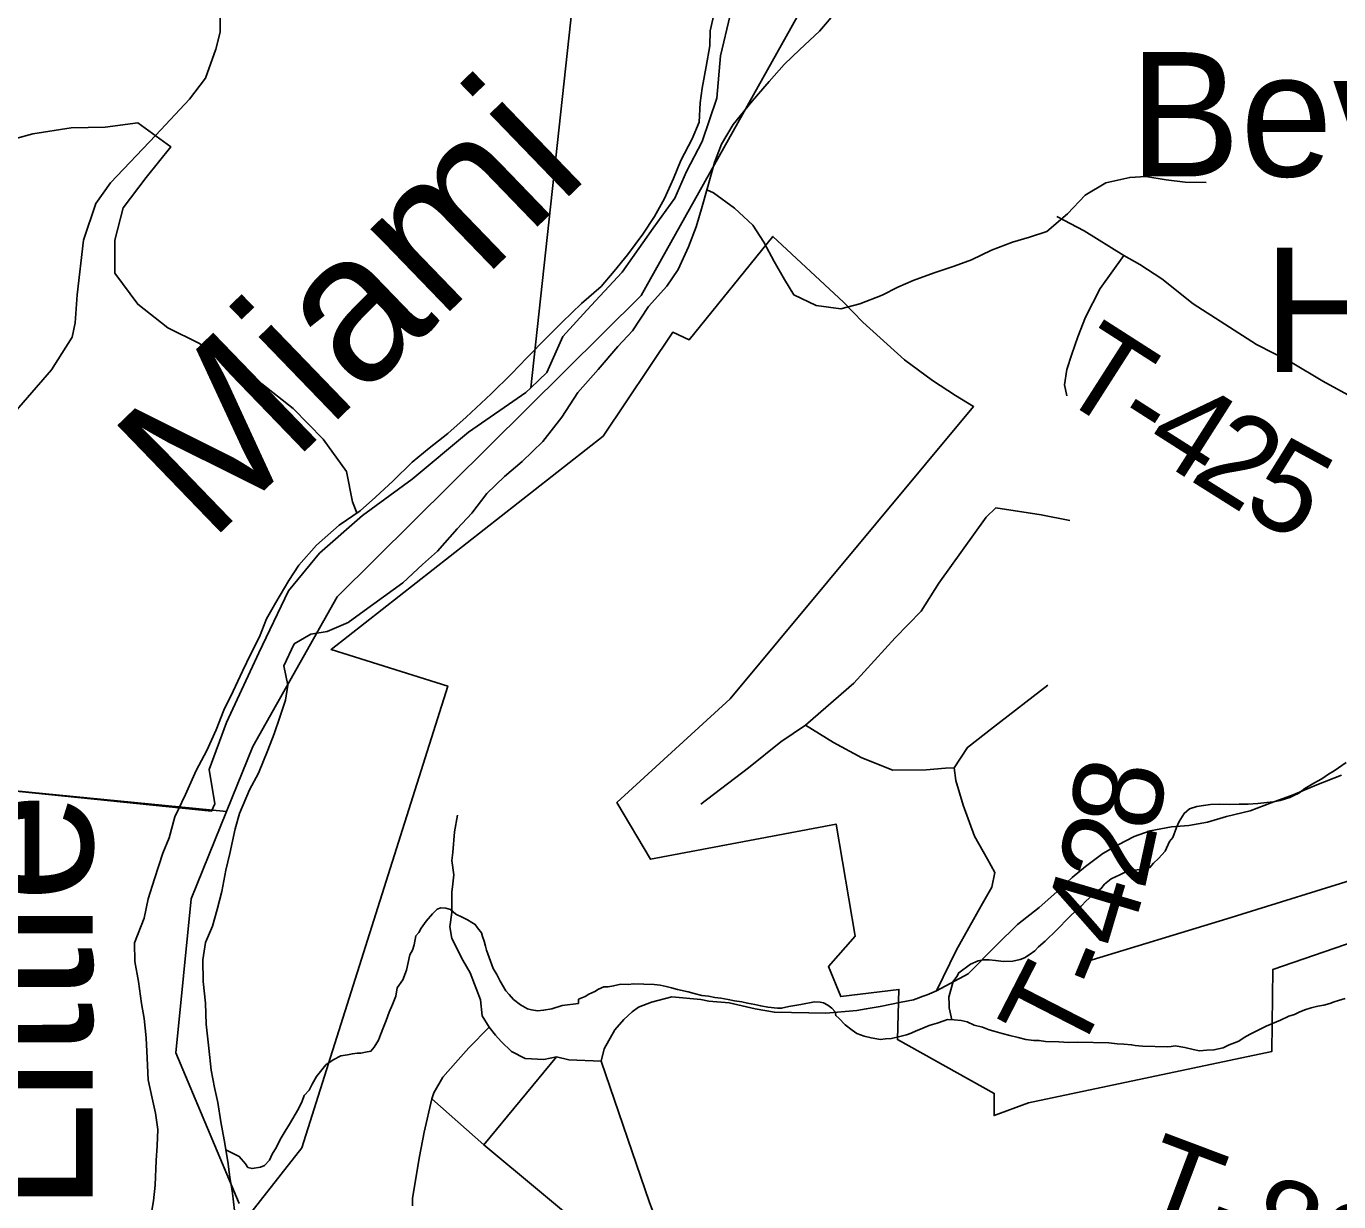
# Model space of a CAD drawing. Extents: x 0 to 34, y 0 to 22.
# Drawn here: x 6.3755 to 6.7924, y 19.556 to 19.9293 of the extents above; entities that cross this region are included whole.
import ezdxf

# ---------------------------------------------------------------- set-up
doc = ezdxf.new("R2010")
doc.units = 0
for name, color, linetype in [('GM_X_City_Street', 7, 'Continuous'), ('GM_X_Corporation', 7, 'Continuous'), ('GM_X_County_Road', 7, 'Continuous'), ('GM_X_Major_River', 7, 'Continuous'), ('GM_X_Major_River_Text', 7, 'Continuous'), ('GM_X_Minor_River', 7, 'Continuous'), ('GM_X_Section', 7, 'Continuous'), ('GM_X_State_Route', 7, 'Continuous'), ('GM_X_Township_Road', 7, 'Continuous'), ('GM_X_Township_Road_Text', 7, 'Continuous'), ('GM_X_Unincorporated_Text', 7, 'Continuous'), ('SH_Cut_Line', 7, 'Continuous')]:
    doc.layers.add(name, color=color, linetype=linetype)

msp = doc.modelspace()

# ---------------------------------------------------------------- linework, layer by layer
at = {"layer": 'GM_X_City_Street'}
msp.add_line((6.52085, 19.57407), (6.54387, 19.60201), dxfattribs=at)
for points in [[(6.55805, 19.60066), (6.54776, 19.6011), (6.54387, 19.60201), (6.53985, 19.60113), (6.53389, 19.60145), (6.52962, 19.60374), (6.52633, 19.60689), (6.52447, 19.60887), (6.5225, 19.61144), (6.5203, 19.61501), (6.51977, 19.62012), (6.51836, 19.62372), (6.51647, 19.62874), (6.51412, 19.63267), (6.51067, 19.63957), (6.51004, 19.64333), (6.51067, 19.64788), (6.51067, 19.65432), (6.51098, 19.65698), (6.5113, 19.65981), (6.51067, 19.66436), (6.51098, 19.66687), (6.51145, 19.67346), (6.51239, 19.67879)], [(6.49811, 19.55474), (6.49811, 19.55603), (6.49813, 19.55709), (6.50035, 19.57038), (6.50182, 19.57804), (6.50425, 19.5887), (6.50497, 19.59062), (6.50781, 19.59555), (6.51176, 19.6001), (6.51603, 19.60492), (6.5225, 19.61144)], [(6.58393, 19.52802), (6.57342, 19.55579), (6.55805, 19.60066)], [(6.5555, 19.54512), (6.52085, 19.57407), (6.50425, 19.5887)]]:
    msp.add_lwpolyline(points, dxfattribs=at)
at = {"layer": 'GM_X_Corporation'}
for points in [[(5.43226, 19.77875), (6.32743, 19.69086), (6.43909, 19.6799), (6.44745, 19.70059), (6.47425, 19.74809), (6.57081, 19.84384), (6.62479, 19.94035), (6.6725, 19.98366), (6.72231, 20.02185), (6.73923, 20.06935), (6.75063, 20.11704), (6.77249, 20.16568), (6.77819, 20.26107)], [(6.77819, 20.26107), (6.77249, 20.16568), (6.75063, 20.11704), (6.73923, 20.06935), (6.72231, 20.02185), (6.6725, 19.98366), (6.62479, 19.94035), (6.57081, 19.84384), (6.47425, 19.74809), (6.44745, 19.70059), (6.43909, 19.6799), (6.42788, 19.65215), (6.42294, 19.60331), (6.4431, 19.55544)], [(6.42905, 19.52976), (6.46297, 19.57308), (6.50933, 19.71976), (6.47227, 19.73135), (6.55869, 19.7991), (6.58087, 19.83221), (6.586, 19.82974), (6.61262, 19.86261), (6.63506, 19.84168), (6.64121, 19.83532), (6.65444, 19.82341), (6.66327, 19.81688), (6.67062, 19.81202), (6.67638, 19.80856), (6.59901, 19.7157), (6.56309, 19.68276), (6.57372, 19.66477), (6.63267, 19.67592), (6.63877, 19.64038), (6.63032, 19.63075), (6.63419, 19.62114), (6.65266, 19.62343), (6.65217, 19.60748), (6.68293, 19.5904), (6.6829, 19.58337), (6.69384, 19.58741), (6.77115, 19.60371), (6.77138, 19.62974), (6.80742, 19.64214)], [(6.4431, 19.55544), (6.42294, 19.60331), (6.42788, 19.65215), (6.43909, 19.6799), (6.32743, 19.69086), (5.43226, 19.77875)]]:
    msp.add_lwpolyline(points, dxfattribs=at)
at = {"layer": 'GM_X_County_Road'}
for points in [[(6.66032, 19.62128), (6.66162, 19.62176), (6.66458, 19.62303), (6.67461, 19.62843), (6.68371, 19.63757), (6.69029, 19.64408), (6.6972, 19.64945), (6.70285, 19.65447), (6.70772, 19.65902), (6.71195, 19.66247), (6.71744, 19.66655), (6.72231, 19.66938), (6.72733, 19.67204), (6.7325, 19.67377), (6.73925, 19.67502), (6.74474, 19.6755), (6.7507, 19.67659), (6.75666, 19.67832), (6.76419, 19.6802), (6.77094, 19.68271), (6.77784, 19.68522), (6.78537, 19.68836), (6.79322, 19.6915)], [(6.55805, 19.60066), (6.55899, 19.60458), (6.56244, 19.61055), (6.56526, 19.61384), (6.56793, 19.61635), (6.56997, 19.61776), (6.57405, 19.61933), (6.58048, 19.62106), (6.58976, 19.62021), (6.59222, 19.61973), (6.59868, 19.61917), (6.607, 19.61729), (6.61311, 19.61619), (6.6294, 19.6159), (6.63924, 19.61676), (6.64225, 19.61725), (6.64668, 19.61803), (6.65334, 19.61934), (6.6573, 19.62015), (6.66032, 19.62128)]]:
    msp.add_lwpolyline(points, dxfattribs=at)
at = {"layer": 'GM_X_Major_River'}
for points in [[(6.59412, 19.93396), (6.59266, 19.92791), (6.59256, 19.92316), (6.59147, 19.91653), (6.59018, 19.90971), (6.58951, 19.90498), (6.58919, 19.8989), (6.58698, 19.89362), (6.58342, 19.88666), (6.58102, 19.88101), (6.57822, 19.87461), (6.57506, 19.86897), (6.57133, 19.86334), (6.56645, 19.85679), (6.56216, 19.85156), (6.55806, 19.8467), (6.55187, 19.84131), (6.54567, 19.83536), (6.54082, 19.83052), (6.53441, 19.824), (6.52956, 19.81896), (6.52316, 19.81263), (6.51522, 19.80519), (6.50941, 19.79999), (6.50342, 19.79536), (6.49801, 19.79091), (6.492, 19.78495), (6.48638, 19.77974), (6.48154, 19.77547), (6.4748, 19.77086), (6.46764, 19.76454), (6.462, 19.7582), (6.45886, 19.75332), (6.45472, 19.74637), (6.45176, 19.74111), (6.44955, 19.73545), (6.44677, 19.73), (6.44419, 19.72454), (6.4412, 19.71814), (6.43822, 19.71212), (6.43581, 19.70589), (6.43282, 19.6993), (6.42945, 19.69291), (6.42606, 19.68538), (6.42268, 19.67822), (6.42083, 19.67161), (6.41882, 19.66671), (6.41618, 19.65859), (6.41414, 19.65216), (6.41287, 19.64611), (6.40985, 19.63819), (6.40992, 19.63229), (6.41111, 19.62599), (6.41209, 19.61894), (6.41294, 19.61417), (6.41357, 19.60808), (6.41381, 19.60161), (6.41423, 19.59476), (6.41543, 19.58884), (6.41646, 19.58407), (6.4173, 19.57891), (6.417, 19.57379), (6.4167, 19.56904), (6.41635, 19.56126), (6.41586, 19.55632), (6.41477, 19.55007)], [(6.44193, 19.55047), (6.44096, 19.55866), (6.44013, 19.56381), (6.43947, 19.56877), (6.4383, 19.57563), (6.43728, 19.58136), (6.43628, 19.58746), (6.43524, 19.59223), (6.43422, 19.59777), (6.43343, 19.60482), (6.43264, 19.61244), (6.43241, 19.61909), (6.43161, 19.62595), (6.43157, 19.6328), (6.43244, 19.63829), (6.43465, 19.64357), (6.43609, 19.64886), (6.43754, 19.65453), (6.43883, 19.66135), (6.44008, 19.66665), (6.44177, 19.67441), (6.4432, 19.67932), (6.44641, 19.68686), (6.44918, 19.69212), (6.45218, 19.69947), (6.45419, 19.70456), (6.45602, 19.70985), (6.45784, 19.71532), (6.45851, 19.72006), (6.45732, 19.72617), (6.46051, 19.73314), (6.46589, 19.73626), (6.47103, 19.7371), (6.47774, 19.74001), (6.48275, 19.7437), (6.49509, 19.75257), (6.50129, 19.75834), (6.50613, 19.76261), (6.51236, 19.76971), (6.51702, 19.77474), (6.52171, 19.78092), (6.52733, 19.78631), (6.53294, 19.79114), (6.53953, 19.79747), (6.54558, 19.80514), (6.55069, 19.81302), (6.55711, 19.8203), (6.56334, 19.82758), (6.56801, 19.83262), (6.57311, 19.8403), (6.57895, 19.84684), (6.58248, 19.85209), (6.58586, 19.85924), (6.58828, 19.86565), (6.58992, 19.87132), (6.59197, 19.8785), (6.59403, 19.88606), (6.59625, 19.89191), (6.59999, 19.89811), (6.60604, 19.90559), (6.61148, 19.91175), (6.61616, 19.91716), (6.6212, 19.922), (6.6274, 19.92777), (6.63304, 19.9343)]]:
    msp.add_lwpolyline(points, dxfattribs=at)
at = {"layer": 'GM_X_Minor_River'}
for points in [[(6.4805, 19.77476), (6.47909, 19.77826), (6.47718, 19.78796), (6.46975, 19.79823), (6.46022, 19.80793), (6.45031, 19.81573), (6.44059, 19.82201), (6.4303, 19.82866), (6.42039, 19.83361), (6.41086, 19.84103), (6.40362, 19.85092), (6.40362, 19.86138), (6.40628, 19.87165), (6.41352, 19.88135), (6.42133, 19.89105), (6.41085, 19.89865), (6.40056, 19.89732), (6.3897, 19.89713), (6.3775, 19.89523), (6.36664, 19.89219)], [(6.59165, 19.87737), (6.59371, 19.87649), (6.60045, 19.8716), (6.60623, 19.86617), (6.60972, 19.86078), (6.61302, 19.85463), (6.61632, 19.84887), (6.61926, 19.84406), (6.62641, 19.84069), (6.63417, 19.83959), (6.64028, 19.84118), (6.64736, 19.84389), (6.65235, 19.84646), (6.65714, 19.84864), (6.66384, 19.85098), (6.67015, 19.85314), (6.6757, 19.85512), (6.68203, 19.85823), (6.68873, 19.86076), (6.69408, 19.86237), (6.69962, 19.86416), (6.70619, 19.86973), (6.71182, 19.8757), (6.71836, 19.87957), (6.72599, 19.88132), (6.73113, 19.8816), (6.73756, 19.88052), (6.74362, 19.87983), (6.75027, 19.8797)], [(6.66947, 19.61378), (6.66856, 19.61759), (6.66859, 19.61873), (6.66846, 19.62101), (6.66909, 19.62327), (6.66991, 19.6259), (6.67109, 19.62758), (6.67169, 19.6287), (6.67537, 19.63145), (6.67786, 19.63252), (6.67939, 19.63286), (6.68129, 19.63281), (6.68337, 19.63257), (6.68584, 19.63231), (6.68888, 19.63242), (6.69117, 19.63293), (6.69251, 19.63346), (6.69405, 19.63437), (6.69579, 19.63565), (6.69697, 19.63695), (6.6991, 19.63879), (6.7028, 19.6423), (6.7067, 19.64637), (6.70903, 19.64858), (6.71059, 19.64987), (6.71215, 19.65153), (6.7139, 19.65319), (6.71564, 19.65466), (6.7168, 19.65539), (6.71798, 19.65688), (6.72011, 19.65853), (6.7228, 19.65979), (6.72453, 19.66069), (6.72682, 19.6612), (6.72911, 19.66152), (6.73121, 19.66184), (6.73236, 19.66219), (6.73353, 19.66349), (6.73509, 19.66496), (6.73723, 19.66737), (6.73864, 19.67037), (6.73962, 19.67167), (6.74084, 19.67486), (6.74165, 19.67674), (6.74323, 19.67935), (6.74498, 19.68082), (6.74728, 19.68152), (6.74937, 19.68184), (6.75166, 19.68216), (6.75451, 19.68228), (6.75774, 19.68219), (6.76078, 19.6823), (6.76363, 19.68223), (6.76667, 19.68253), (6.76953, 19.68283), (6.77162, 19.68297), (6.77372, 19.68348), (6.77545, 19.684), (6.77678, 19.68435), (6.77813, 19.68507), (6.77967, 19.68579), (6.78161, 19.68726), (6.78449, 19.68889), (6.787, 19.69034), (6.78913, 19.6918), (6.79086, 19.69289), (6.79473, 19.69545)], [(6.43884, 19.57246), (6.44309, 19.5704), (6.44512, 19.56807), (6.44585, 19.56691), (6.44717, 19.5665), (6.44984, 19.567), (6.45118, 19.56753), (6.45274, 19.5692), (6.45355, 19.57107), (6.45493, 19.57331), (6.45614, 19.57575), (6.45772, 19.57836), (6.45911, 19.5806), (6.46189, 19.58546), (6.46309, 19.58789), (6.46371, 19.58977), (6.46527, 19.59143), (6.46626, 19.5933), (6.46765, 19.59573), (6.4706, 19.59945), (6.47292, 19.60109), (6.47542, 19.60236), (6.47752, 19.60268), (6.47904, 19.60302), (6.48057, 19.60317), (6.48171, 19.60314), (6.48323, 19.60348), (6.48495, 19.60381), (6.48593, 19.60512), (6.48732, 19.60735), (6.48793, 19.60905), (6.48894, 19.61148), (6.48975, 19.61355), (6.49077, 19.61618), (6.49178, 19.61862), (6.4928, 19.62124), (6.49324, 19.62389), (6.49502, 19.62649), (6.49623, 19.6295), (6.49731, 19.6344), (6.4981, 19.63589), (6.49872, 19.63758), (6.49917, 19.64042), (6.50014, 19.64153), (6.50094, 19.64284), (6.50251, 19.64507), (6.50447, 19.64748), (6.50603, 19.64896), (6.50718, 19.64931), (6.5087, 19.64927), (6.51021, 19.64885), (6.51188, 19.64729), (6.51413, 19.64628), (6.51563, 19.64549), (6.51694, 19.64469), (6.51806, 19.64409), (6.51879, 19.64294), (6.52008, 19.64139), (6.52043, 19.64024), (6.52096, 19.63871), (6.52131, 19.63718), (6.52165, 19.63585), (6.52379, 19.6301), (6.52488, 19.62818), (6.52596, 19.62606), (6.52778, 19.62298), (6.52889, 19.62182), (6.53018, 19.62027), (6.53242, 19.6185), (6.53467, 19.6173), (6.53599, 19.61689), (6.53788, 19.61665), (6.53978, 19.61679), (6.54245, 19.61729), (6.54571, 19.61834), (6.55085, 19.61897), (6.55089, 19.62029), (6.553, 19.62119), (6.55416, 19.62191), (6.55608, 19.62281), (6.55723, 19.62354), (6.55896, 19.62425), (6.56029, 19.62422), (6.56201, 19.62455), (6.5643, 19.62506), (6.56677, 19.625), (6.56829, 19.62515), (6.57493, 19.62497), (6.57683, 19.62473), (6.57871, 19.62431), (6.58041, 19.62388), (6.5823, 19.62345), (6.5857, 19.62261), (6.58759, 19.62218), (6.59004, 19.62154), (6.59212, 19.6213), (6.5942, 19.62087), (6.59609, 19.62063), (6.59836, 19.62019), (6.60044, 19.61976), (6.60271, 19.61951)], [(6.60271, 19.61951), (6.6046, 19.61908), (6.60687, 19.61864), (6.60875, 19.61821), (6.61102, 19.61777), (6.61406, 19.6175), (6.61538, 19.61747), (6.61768, 19.61798), (6.62149, 19.61864), (6.62588, 19.61947), (6.62759, 19.61943), (6.62872, 19.61921), (6.63003, 19.61841), (6.63134, 19.61743), (6.63245, 19.61626), (6.63261, 19.61512), (6.63372, 19.61415), (6.63557, 19.6122), (6.63781, 19.61044), (6.6393, 19.60945), (6.64156, 19.60863), (6.64382, 19.608), (6.64685, 19.60755), (6.64837, 19.6077), (6.65027, 19.60784), (6.65295, 19.60852), (6.65505, 19.60904), (6.65658, 19.60957), (6.65812, 19.61028), (6.66004, 19.61099), (6.66119, 19.61153), (6.66254, 19.61206), (6.66483, 19.61276), (6.66694, 19.61347), (6.66809, 19.61382), (6.67017, 19.61376), (6.67245, 19.61351), (6.67434, 19.61308), (6.67659, 19.61208), (6.67923, 19.61144), (6.6813, 19.61063), (6.68318, 19.61001), (6.68545, 19.60938), (6.6879, 19.60875), (6.69054, 19.60811), (6.69299, 19.60748), (6.69546, 19.60722), (6.69717, 19.60718), (6.69925, 19.60693), (6.70342, 19.60682), (6.70664, 19.60655), (6.7095, 19.60667), (6.71937, 19.60641), (6.72202, 19.60615), (6.72411, 19.60609), (6.72657, 19.60584), (6.7277, 19.60562), (6.72997, 19.60537), (6.73795, 19.60516), (6.73909, 19.60532), (6.74042, 19.60548), (6.74345, 19.60502), (6.74609, 19.60438), (6.74817, 19.60395), (6.75045, 19.60408), (6.75273, 19.60421), (6.7556, 19.60489), (6.75752, 19.60579), (6.75925, 19.6065), (6.76059, 19.60704), (6.76233, 19.60813), (6.76426, 19.60922), (6.76926, 19.61174), (6.77386, 19.6137), (6.77655, 19.61496), (6.77828, 19.61549), (6.77981, 19.6162), (6.78154, 19.61692), (6.78365, 19.61762), (6.78575, 19.61813), (6.78766, 19.61846), (6.78957, 19.61898), (6.79091, 19.61951), (6.79225, 19.61986), (6.79436, 19.62056)]]:
    msp.add_lwpolyline(points, dxfattribs=at)
at = {"layer": 'GM_X_Section'}
msp.add_lwpolyline([(5.98888, 20.23965), (6.57479, 20.17408), (6.53576, 19.81452), (6.53419, 19.81301), (6.51594, 19.8004), (6.49801, 19.78545), (6.48222, 19.77393), (6.46855, 19.76197), (6.45874, 19.75002), (6.44934, 19.73038), (6.4391, 19.70818), (6.43355, 19.69324), (6.43532, 19.6824), (6.43432, 19.68006), (5.94132, 19.73044)], close=True, dxfattribs=at)
msp.add_lwpolyline([(6.5991, 19.93291), (6.596, 19.9199), (6.59478, 19.90648), (6.59015, 19.89275), (6.58522, 19.88319), (6.58146, 19.87475), (6.57464, 19.86523), (6.5647, 19.85122), (6.55347, 19.83914), (6.54592, 19.83077), (6.54085, 19.81941), (6.53576, 19.81452), (6.57479, 20.17408)], dxfattribs=at)
at = {"layer": 'GM_X_State_Route'}
msp.add_lwpolyline([(6.43714, 19.93717), (6.43708, 19.92747), (6.43568, 19.92202), (6.43241, 19.91286), (6.42736, 19.90624), (6.41658, 19.89477), (6.40222, 19.87965), (6.39754, 19.87302), (6.39359, 19.86142), (6.39164, 19.84401), (6.39103, 19.83511), (6.39007, 19.83059), (6.38352, 19.82024), (6.35145, 19.78351)], dxfattribs=at)
at = {"layer": 'GM_X_Township_Road'}
for points in [[(6.83856, 19.79426), (6.81079, 19.80445), (6.79759, 19.81104), (6.78727, 19.81663), (6.77703, 19.82277), (6.76623, 19.8283), (6.74615, 19.84116), (6.73616, 19.84912), (6.72922, 19.85369), (6.72414, 19.85657), (6.71148, 19.86438), (6.70282, 19.86892)], [(6.72414, 19.85657), (6.71657, 19.84601), (6.71195, 19.83693), (6.70944, 19.83065), (6.70756, 19.82516), (6.70599, 19.8203), (6.70521, 19.81544), (6.70599, 19.81198)], [(6.58972, 19.68223), (6.60484, 19.69378), (6.61514, 19.70202), (6.62297, 19.70738), (6.63836, 19.72071), (6.65142, 19.73514), (6.65967, 19.74352), (6.6653, 19.7525), (6.68033, 19.77342), (6.68346, 19.77639), (6.6978, 19.77413), (6.70692, 19.77241)], [(6.66458, 19.62303), (6.67092, 19.63598), (6.67879, 19.65002), (6.68218, 19.65594), (6.68311, 19.6606), (6.68082, 19.66483), (6.67668, 19.67211), (6.67304, 19.682), (6.67075, 19.68979), (6.67025, 19.69377), (6.67441, 19.70027), (6.6827, 19.70674), (6.69991, 19.72011)], [(6.67025, 19.69377), (6.66743, 19.69367), (6.66131, 19.69312), (6.65073, 19.69309), (6.64084, 19.69694), (6.63191, 19.70188), (6.62297, 19.70738)], [(6.80249, 19.66004), (6.75684, 19.64587), (6.71158, 19.63206)]]:
    msp.add_lwpolyline(points, dxfattribs=at)
at = {"layer": 'SH_Cut_Line'}
for points in [[(6.4431, 19.55544), (6.42294, 19.60331), (6.42788, 19.65215), (6.43909, 19.6799), (6.44745, 19.70059), (6.47425, 19.74809), (6.57081, 19.84384), (6.62479, 19.94035), (6.6725, 19.98366), (6.72231, 20.02185), (6.73923, 20.06935), (6.75063, 20.11704), (6.77249, 20.16568), (6.77819, 20.26107)], [(6.77819, 20.26107), (6.77249, 20.16568), (6.75063, 20.11704), (6.73923, 20.06935), (6.72231, 20.02185), (6.6725, 19.98366), (6.62479, 19.94035), (6.57081, 19.84384), (6.47425, 19.74809), (6.44745, 19.70059), (6.43909, 19.6799), (6.42788, 19.65215), (6.42294, 19.60331), (6.4431, 19.55544)]]:
    msp.add_lwpolyline(points, dxfattribs=at)

# ---------------------------------------------------------------- texts
at = {"layer": 'GM_X_Major_River_Text'}
for s, height, rotation, p in [('Miami', 0.047336, 43.9949, (6.43352, 19.76495)), ('Little', 0.047335, 90.0081, (6.39652, 19.55253))]:
    msp.add_text(s, height=height, rotation=rotation, dxfattribs=at).set_placement(p)
at = {"layer": 'GM_X_Township_Road_Text'}
for s, height, rotation, p in [('T', 0.02841, 327.3845, (6.70177, 19.81277)), ('4', 0.02841, 327.5006, (6.72955, 19.795)), ('-', 0.02841, 327.4107, (6.71968, 19.80131)), ('2', 0.02841, 327.8313, (6.74446, 19.78551)), ('5', 0.02841, 331.3848, (6.76093, 19.77522)), ('8', 0.02841, 80.2847, (6.73453, 19.67293)), ('2', 0.02841, 77.791, (6.73057, 19.6545)), ('4', 0.02841, 73.4204, (6.72499, 19.63544)), ('-', 0.02841, 67.5491, (6.71948, 19.62167)), ('T', 0.02841, 62.8542, (6.70872, 19.60045)), ('T-82', 0.028409, 339.387, (6.72655, 19.55154))]:
    msp.add_text(s, height=height, rotation=rotation, dxfattribs=at).set_placement(p)
at = {"layer": 'GM_X_Unincorporated_Text'}
for s, p in [('Beverly', (6.72587, 19.88164)), ('Hills', (6.76837, 19.81956))]:
    msp.add_text(s, height=0.039489, rotation=0, dxfattribs=at).set_placement(p)

doc.saveas('drawing.dxf')
